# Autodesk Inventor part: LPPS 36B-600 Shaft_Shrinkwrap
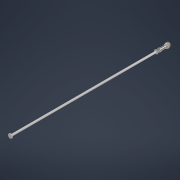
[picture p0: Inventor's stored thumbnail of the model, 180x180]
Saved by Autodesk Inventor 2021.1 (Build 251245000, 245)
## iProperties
Created: 2020-09
Part Number: LPPS 36B-600 Shaft_Shrinkwrap
Material: Generic
Document SubType Name: Modeling
Designer: J. Nielson
Density: 1 g/cm^3
Appearance: Default
Author: J. Nielson
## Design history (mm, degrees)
derived "LPPS 36B-600.iam"
body "Solid1"
node "LPPS-36B-600 ROD.ipt:1"
node "Custom Flanged Nut.ipt:1"
body "Solid2"
node "FEMALE Rod End SW.ipt:1"
body "Solid3"
node "JIS B 1181 - M8x1(4).ipt:1"
body "Solid4"
